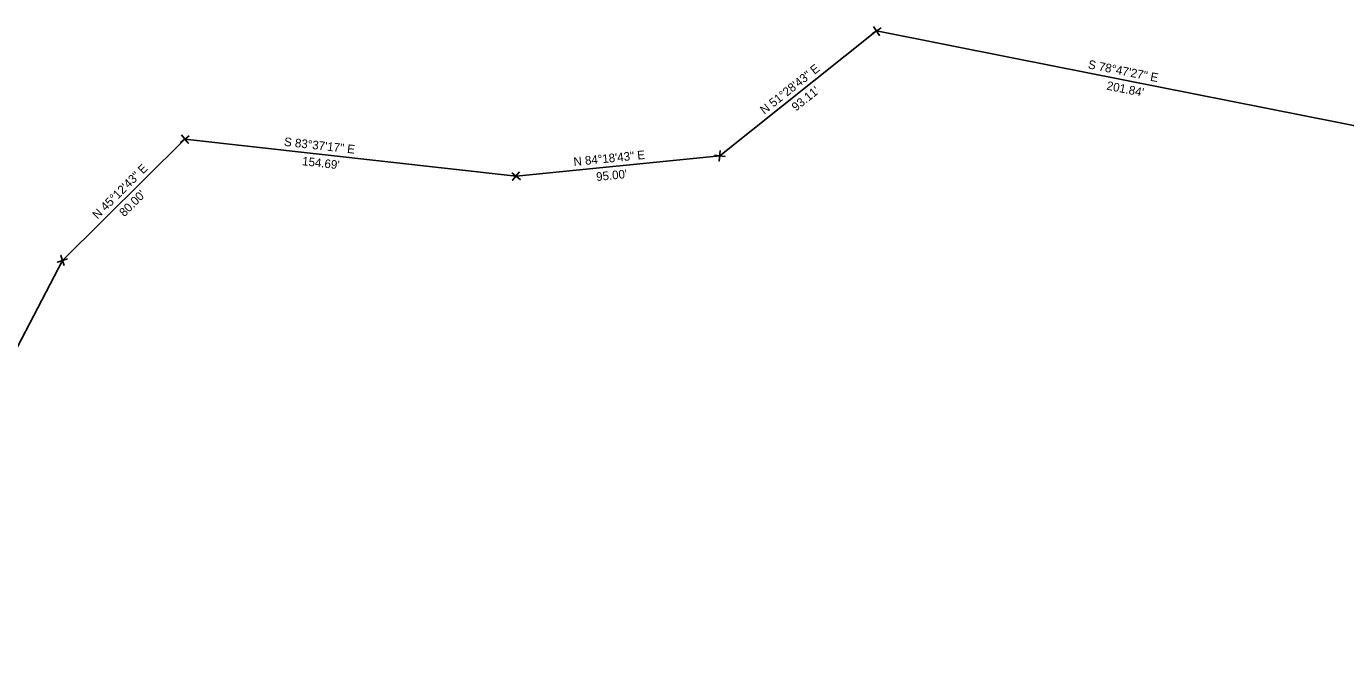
# Model space of a CAD drawing. Extents: x 1316460 to 1321645, y 684173 to 687077.
# Drawn here: x 1319876 to 1320489, y 686398 to 686693 of the extents above; entities that cross this region are included whole.
import ezdxf

# ---------------------------------------------------------------- set-up
doc = ezdxf.new("R2010")
doc.units = 0
for name, color, linetype in [('Exist Property Corner CELL', 7, 'Continuous'), ('Exist Property Line', 7, 'Continuous'), ('Exist Property Line Text', 7, 'Continuous')]:
    doc.layers.add(name, color=color, linetype=linetype)

msp = doc.modelspace()

# ---------------------------------------------------------------- linework, layer by layer
at = {"layer": 'Exist Property Corner CELL'}
for p, q in [((1320271.11, 686690.79), (1320271.11, 686690.79)), ((1319950, 686640.57), (1319950, 686640.57)), ((1320198.26, 686632.8), (1320198.26, 686632.8)), ((1320103.73, 686623.39), (1320103.73, 686623.39)), ((1319893.22, 686584.21), (1319893.22, 686584.21))]:
    msp.add_line(p, q, dxfattribs=at)
for points in [[(1320273.19, 686692.18), (1320269.03, 686689.4), (1320271.11, 686690.79), (1320272.5, 686688.71), (1320269.72, 686692.87)], [(1319951.95, 686642.13), (1319948.05, 686639.01), (1319950, 686640.57), (1319951.56, 686638.62), (1319948.44, 686642.52)], [(1320198.55, 686635.29), (1320197.98, 686630.32), (1320198.26, 686632.8), (1320200.75, 686632.52), (1320195.78, 686633.08)], [(1320105.31, 686625.32), (1320102.15, 686621.45), (1320103.73, 686623.39), (1320105.67, 686621.8), (1320101.8, 686624.97)], [(1319893.97, 686581.83), (1319892.47, 686586.6), (1319893.22, 686584.21), (1319890.84, 686583.46), (1319895.61, 686584.96)]]:
    msp.add_lwpolyline(points, dxfattribs=at)
at = {"layer": 'Exist Property Line'}
for p, q in [((1320198.26, 686632.8), (1320271.11, 686690.79)), ((1320271.11, 686690.79), (1320334.73, 686678.18)), ((1320334.73, 686678.18), (1320532.72, 686638.95)), ((1319893.22, 686584.21), (1319950, 686640.57)), ((1319950, 686640.57), (1320103.73, 686623.39)), ((1320103.73, 686623.39), (1320198.26, 686632.8)), ((1319731.27, 686273.93), (1319893.22, 686584.21))]:
    msp.add_line(p, q, dxfattribs=at)

# ---------------------------------------------------------------- texts
at = {"layer": 'Exist Property Line Text'}
for s, rotation, p in [('N 51%%D28\'43" E', 38.52139, (1320218.99, 686651.85)), ('S 78%%D47\'27" E', 348.79083, (1320368.98, 686673.43)), ("201.84'", 348.79083, (1320377.63, 686663.56)), ("93.11'", 38.52139, (1320233.64, 686653.29)), ('S 83%%D37\'17" E', 353.62139, (1319995.91, 686637.45)), ("154.69'", 353.62139, (1320004.3, 686628.46)), ('N 84%%D18\'43" E', 5.68806, (1320130.6, 686628.07)), ('N 45%%D12\'43" E', 44.78806, (1319909.46, 686603.15)), ("95.00'", 5.68806, (1320141.12, 686621.08)), ("80.00'", 44.78806, (1319921.92, 686604.25))]:
    msp.add_text(s, height=4, rotation=rotation, dxfattribs=at).set_placement(p)

doc.saveas('drawing.dxf')
